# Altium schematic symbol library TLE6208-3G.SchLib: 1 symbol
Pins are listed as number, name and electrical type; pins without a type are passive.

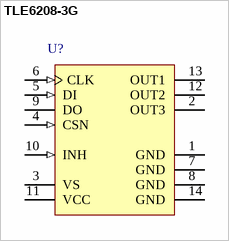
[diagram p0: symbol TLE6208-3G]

## TLE6208-3G
designator U?
Triple Half-Bridge Driver IC, -40 to 150 degC, PG-DSO-14-35, Reel, Green; Manufacturer: Infineon; PartNumber: TLE6208-3G; Green: TRUE; Group: Multi Half Bridges; IPeak: 3 x 1.2 A; Iq: 3 x 0.6 A; Iq (typ): 10 uA; Protect: short circuit e.a.
footprint INF-PG-DSO-14-35_N (SOP, 14-Leads, Body 8.65x3.9mm, Pitch 1.27mm, IPC Medium Density)
footprint INF-PG-DSO-14-35_L (SOP, 14-Leads, Body 8.65x3.9mm, Pitch 1.27mm, IPC High Density)
footprint INF-PG-DSO-14-35_M (SOP, 14-Leads, Body 8.65x3.9mm, Pitch 1.27mm, IPC Low Density)
pins: 1 GND (power) "Ground; Reference potential; internal connection to pin 7, 8 and 14; cooling tab; to reduce thermal resistance place cooling areas on PCB close to these pins.", 2 OUT3 (power) "Halfbridge-Output 3;Internally contected to Highside-Switch 3 and Lowside-Switch 3. The HS-Switch is a Power-MOS open drain with internal reverse diode; The LS-Switch is a Power-MOS open source with internal reverse diode; (See Datasheet)", 3 VS (power) "Power Supply; needs a blocking capacitor as close as possible to GND Value: 22 uF electrolytic in parallel to 220 nF ceramic.", 4 CSN (in) "Chip-Select-Not Input; CSN is an active low input; serial communication is enabled by pulling the CSN terminal low; CSN input should only be transitioned when CLK is low; CSN has an internal active pull up and requires CMOS (See Datasheet)", 5 DI (in) "Serial Data Input; receives serial data from the control device; serial data transmitted to DI is an 16bit control word with the Least Significant Bit (LSB) being transferred first: the input has an active pull down and (See Datasheet)", 6 CLK (in) "Serial Clock Input; clocks the shiftregister; CLK has an internal active pull down and requires CMOS logic level inputs.", 7 GND (power) "Ground; Reference potential; internal connection to pin 7, 8 and 14; cooling tab; to reduce thermal resistance place cooling areas on PCB close to these pins.", 8 GND (power) "Ground; Reference potential; internal connection to pin 7, 8 and 14; cooling tab; to reduce thermal resistance place cooling areas on PCB close to these pins.", 9 DO (hiz) "Serial-Data-Output; this 3-state output transfers diagnosis data to the control device; the output will remain 3-stated unless the device is selected by a low on Chip-Select-Not (CSN); see Table Diagnosis Data Protocol.", 10 INH (in) "Inhibit Input; has an internal pull down; device is switched in standby condition by pulling the INH terminal low.", 11 VCC (power) "Logic Supply Voltage; needs a blocking capacitor as close as possible to GND; Value: 10 µF electrolytic in parallel to 220 nF ceramic.", 12 OUT2 (power) "Halfbridge-Output 2;Internally contected to Highside-Switch 2 and Lowside-Switch 2. The HS-Switch is a Power-MOS open drain with internal reverse diode; The LS-Switch is a Power-MOS open source with internal reverse diode; (See Datasheet)", 13 OUT1 (power) "Halfbridge-Output 1;Internally contected to Highside-Switch 1 and Lowside-Switch 1. The HS-Switch is a Power-MOS open drain with internal reverse diode; The LS-Switch is a Power-MOS open source with internal reverse diode; (See Datasheet)", 14 GND (power) "Ground; Reference potential; internal connection to pin 7, 8 and 14; cooling tab; to reduce thermal resistance place cooling areas on PCB close to these pins."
